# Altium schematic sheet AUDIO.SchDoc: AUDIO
size A4; Author: P.A.; CompanyName: STMicroelectronics; Organization: Microcontrollers Division; Address1: 12, Rue Jules HOROWITZ; Address2: 38019 Grenoble; Address3: FRANCE; DocumentNumber: MB1272; Revision: A-01; SheetNumber: 7; SheetTotal: 15; Project: STM32MP15-DISCO PI
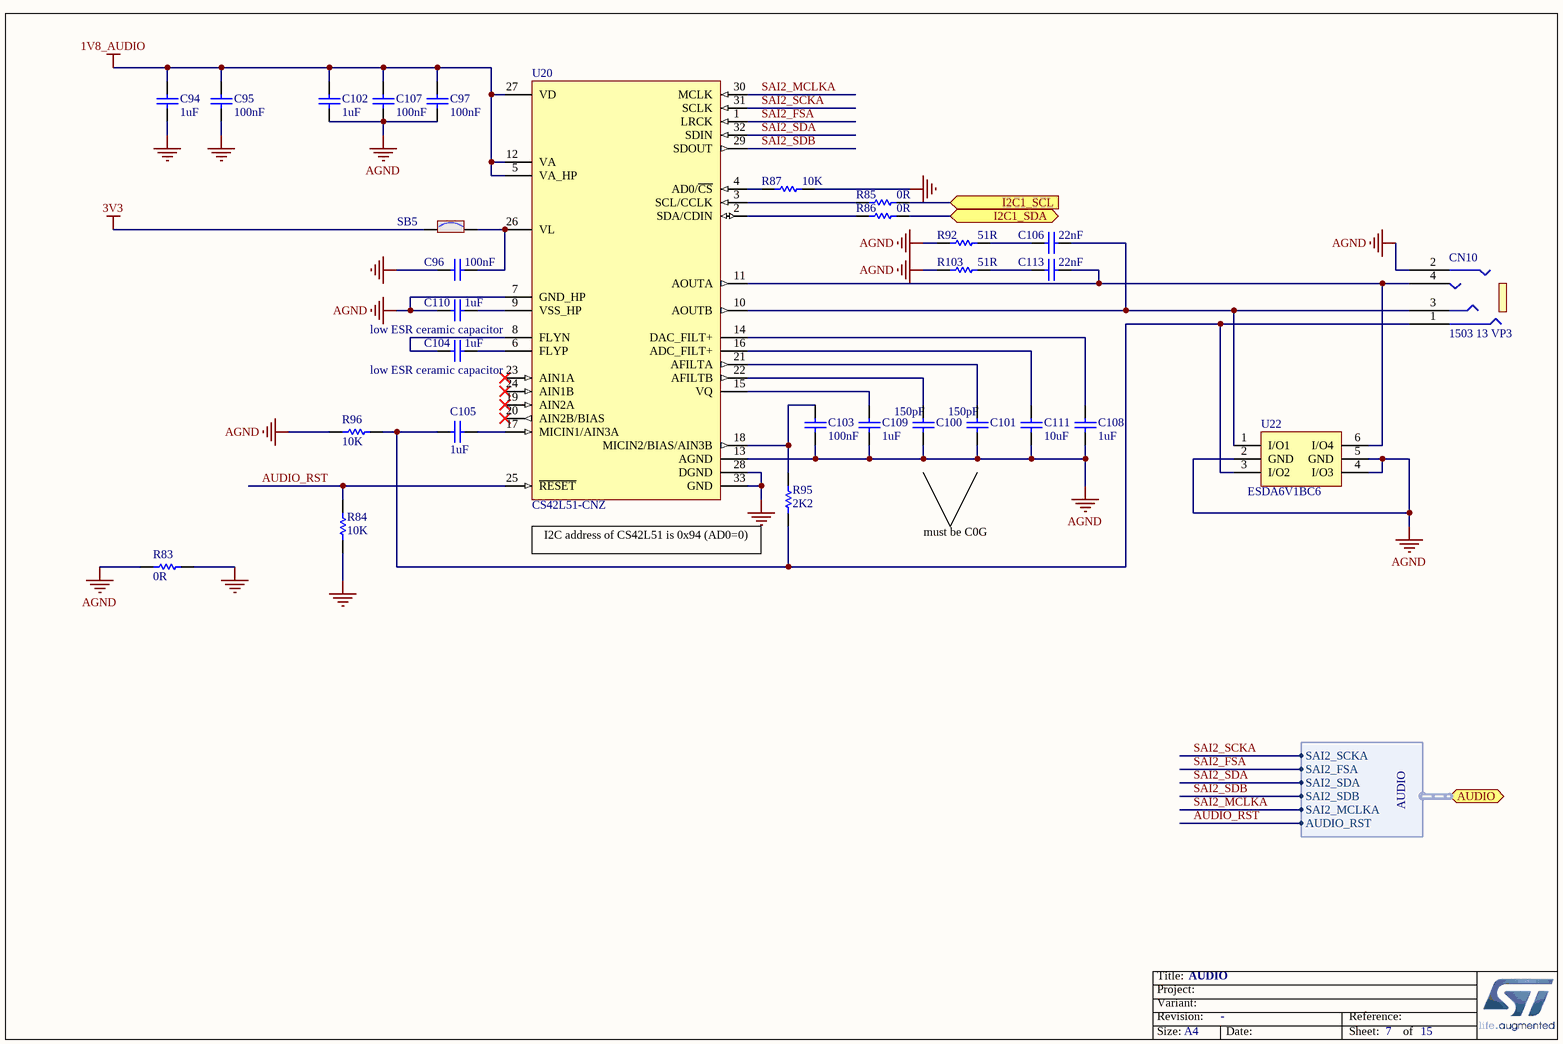
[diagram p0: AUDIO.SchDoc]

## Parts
C94  value 1uF  [C0402]
C95  value 100nF  [C0402]
C96  value 100nF  [C0402]
C97  value 100nF  [C0402]
C100  value 150pF  [C0603]
C101  value 150pF  [C0603]
C102  value 1uF  [C0402]
C103  value 100nF  [C0402]
C104  value 1uF  [C0603]
C105  value 1uF  [C0402]
C106  value 22nF  [C0402]
C107  value 100nF  [C0402]
C108  value 1uF  [C0402]
C109  value 1uF  [C0402]
C110  value 1uF  [C0603]
C111  value 10uF  [C0603]
C113  value 22nF  [C0402]
CN10  value 1503 13 VP3  [CON_JACK-3P5-SMT_LUMBERG_1503-13-VP3]
R83  value 0R  [R0603]
R84  value 10K  [R0402]
R85  value 0R  [R0402]
R86  value 0R  [R0402]
R87  value 10K  [R0402]
R92  value 51R  [R0402]
R95  value 2K2  [R0402]
R96  value 10K  [R0402]
R103  value 51R  [R0402]
SB5  (no value)  [SOLDER-BRIDGE_R0603-0R]
U20  value CS42L51-CNZ  [ICC_QFN32-EPAD_5X5_P050]
U22  value ESDA6V1BC6  [ESD_SOT23-6L]

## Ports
AUDIO (harness AUDIO), I2C1_SCL (in), I2C1_SDA (bidir)

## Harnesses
AUDIO: SAI2_SCKA, SAI2_FSA, SAI2_SDA, SAI2_SDB, SAI2_MCLKA, AUDIO_RST

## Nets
1V8_AUDIO: C94.2 C95.2 C97.2 C102.2 C107.2 U20.5(VA_HP) U20.12(VA) U20.27(VD)
3V3: SB5.1
AGND: C97.1 C100.1 C101.1 C102.1 C103.1 C107.1 C108.1 C109.1 C110.1 C111.1 CN10.2 R83.1 R92.1 R96.1 R103.1 U20.7(GND_HP) U20.13(AGND) U22.2(GND) U22.4(I/O3) U22.5(GND)
GND: C94.1 C95.1 C96.2 R83.2 R84.1 R87.2 U20.28(DGND) U20.33(GND)
AUDIO_RST: R84.2 U20.25(~{RESET}) ; port AUDIO.AUDIO_RST
I2C1_SCL: R85.2 ; port I2C1_SCL
I2C1_SDA: R86.2 ; port I2C1_SDA
SAI2_FSA: U20.1(LRCK) ; port AUDIO.SAI2_FSA
SAI2_MCLKA: U20.30(MCLK) ; port AUDIO.SAI2_MCLKA
SAI2_SCKA: U20.31(SCLK) ; port AUDIO.SAI2_SCKA
SAI2_SDA: U20.32(SDIN) ; port AUDIO.SAI2_SDA
SAI2_SDB: U20.29(SDOUT) ; port AUDIO.SAI2_SDB
NetC96_1: C96.1 SB5.2 U20.26(VL)
NetC100_2: C100.2 U20.22(AFILTB)
NetC101_2: C101.2 U20.21(AFILTA)
NetC103_2: C103.2 R95.2 U20.18(MICIN2/BIAS/AIN3B)
NetC104_1: C104.1 U20.8(FLYN)
NetC104_2: C104.2 U20.6(FLYP)
NetC105_1: C105.1 CN10.1 R95.1 R96.2 U22.3(I/O2)
NetC105_2: C105.2 U20.17(MICIN1/AIN3A)
NetC106_1: C106.1 R92.2
NetC106_2: C106.2 CN10.3 U20.10(AOUTB) U22.1(I/O1)
NetC108_2: C108.2 U20.14(DAC_FILT+)
NetC109_2: C109.2 U20.15(VQ)
NetC110_2: C110.2 U20.9(VSS_HP)
NetC111_2: C111.2 U20.16(ADC_FILT+)
NetC113_1: C113.1 R103.2
NetC113_2: C113.2 CN10.4 U20.11(AOUTA) U22.6(I/O4)
NetR85_1: R85.1 U20.3(SCL/CCLK)
NetR86_1: R86.1 U20.2(SDA/CDIN)
NetR87_1: R87.1 U20.4(AD0/~{CS})

Not connected (* = marked no-connect by the designer): U20 19(AIN2A)* 20(AIN2B/BIAS)* 23(AIN1A)* 24(AIN1B)*

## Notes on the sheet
- low ESR ceramic capacitor
- I2C address of CS42L51 is 0x94 (AD0=0)
- must be C0G

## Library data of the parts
C94 C102 C105 C108 C109 = MCD-00095: Capacitor,1uF,6V3,X5R,10%,0402; Manufacturer_Part_Number: GRM155R61E105KA12; Manufacturer: MURATA; Alternate_Manufacturer_Part_Number: GRM155R60J105KE19; ECCN_US: EAR99; ECCN_EU: NEC; Provided_By: SUBCO; Initial_Board_Reference: mb1262
C95-C97 C103 C107 = MCD-00006: Capacitor,100nF,16V,X7R,10%,0402; Manufacturer_Part_Number: CC0402KRX7R7BB104; Manufacturer: YAGEO; Alternate_Manufacturer: MURATA; Alternate_Manufacturer_Part_Number: GCM155R71C104KA55D; Provided_By: SUBCO; Initial_Board_Reference: mb1274
C100 C101 = MCD-00304: Capacitor,150pF,50V,COG,5%,0603; Manufacturer_Part_Number: CC0603JRNPO9BN151; Manufacturer: YAGEO; Provided_By: SUBCO; Initial_Board_Reference: mb1263
C104 C110 = MCD-00010: Capacitor,1uF,16V,X5R,10%,0603; Manufacturer_Part_Number: CC0603KRX5R7BB105; Manufacturer: YAGEO; Provided_By: SUBCO; Initial_Board_Reference: mb1274
C106 C113 = MCD-00202: Capacitor,22nF,16V,X7R,10%,0402; Manufacturer_Part_Number: CC0402KRX7R7BB223; Manufacturer: YAGEO; Provided_By: SUBCO
C111 = MCD-00098: Capacitor,10uF,6V3,X5R,10%,0603; Manufacturer_Part_Number: CC0603KRX5R5BB106; Manufacturer: YAGEO; Provided_By: SUBCO; Initial_Board_Reference: mb1262
CN10 = MCD-00270: Connector Jack socket Stereo 3.5mm, 4 pins, RA, SMT, Black; Manufacturer: LUMBERG; Alternate_Manufacturer: FARNELL; Alternate_Manufacturer_Part_Number: 1368640; Provided_By: SUBCO; Initial_Board_Reference: MB1272
R83 = MCD-00056: Resistor,0R,0603,5%,1/10W; Manufacturer_Part_Number: RC0603JR-070RL; Manufacturer: YAGEO; Provided_By: SUBCO; Initial_Board_Reference: mb1274
R84 R87 R96 = MCD-00053: Resistor,10K,0402,1%,1/16W; Manufacturer_Part_Number: RC0402FR-0710KL; Manufacturer: YAGEO; Provided_By: SUBCO; Initial_Board_Reference: mb1274
R85 R86 = MCD-00052: Resistor,0R,0402,5%,1/16W; Manufacturer_Part_Number: RC0402JR-070RL; Manufacturer: YAGEO; Provided_By: SUBCO; Initial_Board_Reference: mb1274
R92 R103 = MCD-00485: Resistor,51R,0402,1%,1/16W; Manufacturer_Part_Number: RC0402FR-0751RL; Manufacturer: YAGEO; Provided_By: SUBCO
R95 = MCD-00057: Resistor,2K2,0402,1%,1/16W; Manufacturer_Part_Number: RC0402FR-072K2L; Manufacturer: YAGEO; Provided_By: SUBCO; Initial_Board_Reference: mb1274
SB5 = MCD-00071: Solder Bridge ON; Part_Type: Mechanical; Manufacturer: YAGEO; Manufacturer_Part_Number: RC0603JR-070RL; Provided_By: SUBCO; Initial_Board_Reference: mb1274
U20 = MCD-00265: Low-Power, Stereo Codec with Headphone Amp; Manufacturer: CIRRUS LOGIC; Part_Type: IC; Provided_By: SUBCO; ECCN_US: EAR99; ECCN_EU: NEC; Initial_Board_Reference: MB1272
U22 = MCD-00247: Quad Bidir ESD protection; Manufacturer: STMICROELECTRONICS; Part_Type: Diode; BMS_Part_Number: 9179038; Provided_By: SUBCO with ST control; ECCN_US: EAR99; ECCN_EU: NEC; Initial_Board_Reference: MB1311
